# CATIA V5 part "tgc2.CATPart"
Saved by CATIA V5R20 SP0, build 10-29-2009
Part number: TGC2
Revision: 2
Definition: design
Nomenclature: TGC2
Source: made
Description: NOT SPECIFIED
Bounding box of the stored display mesh (mm): x -2.9 to 22.1, y -5 to 5, z -19 to 3
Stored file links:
  C:\Users\Utente\Desktop\IO LAVORO\3D X SITO CF\X SITO\PLASTICA\TGC-XS\tgc2.CATPart
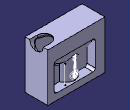
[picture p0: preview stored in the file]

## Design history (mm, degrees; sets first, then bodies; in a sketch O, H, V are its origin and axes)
Set1
  Line1 "LINE #4390": stored without definition
  DatumCurve1 "COMPOSITE_CURVE #4531"
  DatumCurve2 "COMPOSITE_CURVE #4763"
  DatumCurve3 "COMPOSITE_CURVE #4790"
  DatumCurve4 "COMPOSITE_CURVE #4852"
  DatumCurve5 "COMPOSITE_CURVE #4908"
  DatumCurve6 "COMPOSITE_CURVE #4935"
  DatumCurve7 "COMPOSITE_CURVE #5018"
  DatumCurve8 "COMPOSITE_CURVE #5061"
  DatumCurve9 "COMPOSITE_CURVE #5112"
  DatumCurve10 "COMPOSITE_CURVE #5163"
  DatumSurface1 "OPEN_SHELL #4230"
  DatumSurface2 "OPEN_SHELL #4283"
  DatumSurface3 "OPEN_SHELL #4380"
Body1 "MANIFOLD_SOLID_BREP #4381" (main body)
  Solid1: solid without history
